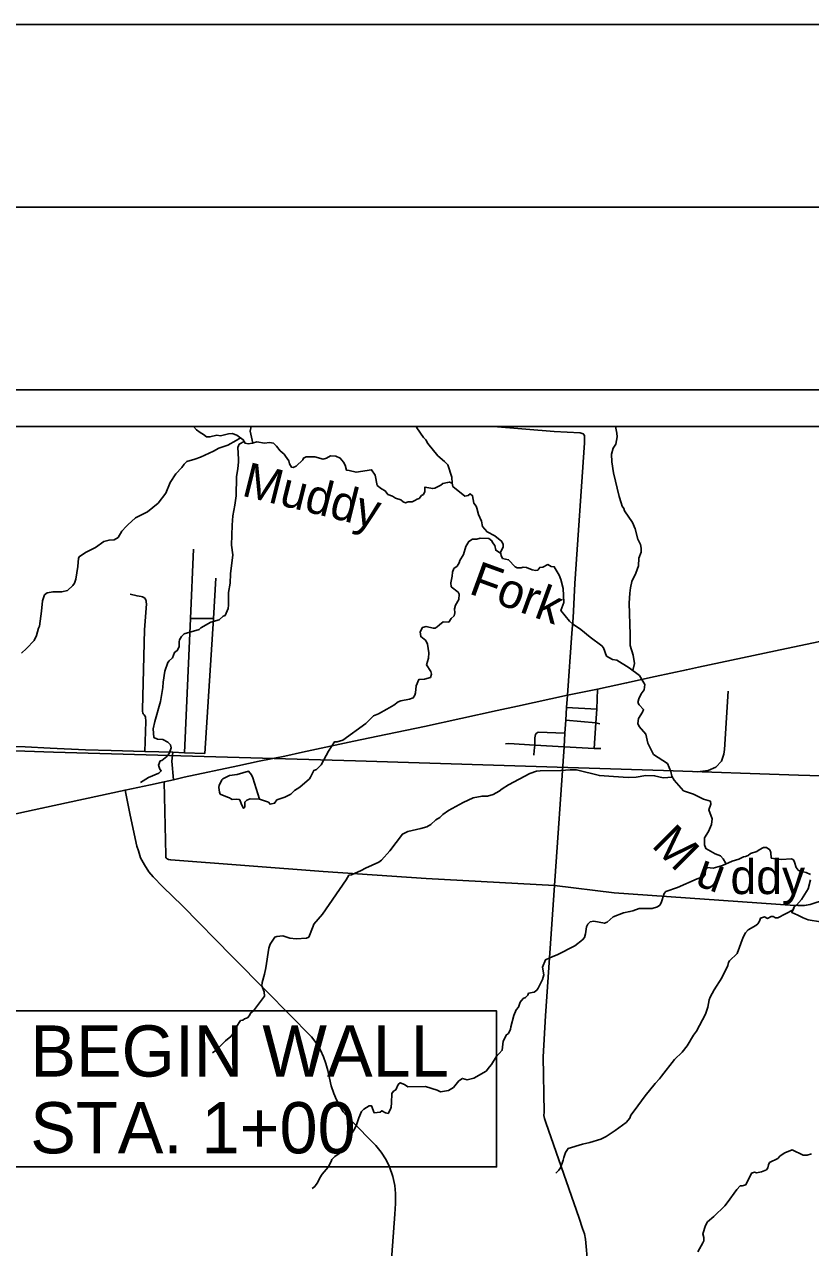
# Model space of a CAD drawing. Extents: x 0 to 34, y 0 to 22.
# Drawn here: x 3.646 to 5.796, y 18.654 to 22 of the extents above; entities that cross this region are included whole.
import ezdxf

# ---------------------------------------------------------------- set-up
doc = ezdxf.new("R2010")
doc.units = 0
for name, color, linetype in [('GM_X_City_Street', 7, 'Continuous'), ('GM_X_Corporation', 7, 'Continuous'), ('GM_X_Minor_Lake', 7, 'Continuous'), ('GM_X_Minor_River', 7, 'Continuous'), ('GM_X_Minor_River_Text', 7, 'Continuous'), ('GM_X_Rail_Line', 7, 'Continuous'), ('GM_X_State_Route', 7, 'Continuous'), ('GM_X_Township_Road', 7, 'Continuous'), ('SH_Border', 7, 'Continuous'), ('SH_Cut_Line', 7, 'Continuous'), ('SH_Data', 7, 'Continuous'), ('SH_Text', 7, 'Continuous')]:
    doc.layers.add(name, color=color, linetype=linetype)

msp = doc.modelspace()

# ---------------------------------------------------------------- linework, layer by layer
at = {"layer": 'GM_X_City_Street'}
for p, q in [((4.1002, 20.3749), (4.1627, 20.3752)), ((5.1287, 20.131), (5.2113, 20.1263))]:
    msp.add_line(p, q, dxfattribs=at)
for points in [[(8.3697, 20.9), (2.1, 20.9)], [(4.0842, 20.007), (4.1002, 20.3749), (4.1085, 20.5648)], [(4.1393, 20.005), (4.1627, 20.3752), (4.1696, 20.4851)], [(3.975, 20.0109), (3.9777, 20.0929), (3.9772, 20.1055), (3.9736, 20.1111), (3.971, 20.1139), (3.9696, 20.1166), (3.9688, 20.1202), (3.9688, 20.1262), (3.9749, 20.3433), (3.9797, 20.4151), (3.979, 20.4196), (3.979, 20.423), (3.9782, 20.4253), (3.976, 20.4291), (3.973, 20.4318), (3.9692, 20.4337), (3.9658, 20.4349), (3.9544, 20.4364), (3.9351, 20.4414)], [(5.2039, 20.0192), (5.2086, 20.0889), (5.2113, 20.1263), (5.2134, 20.1816)], [(5.127, 20.0967), (5.2086, 20.0889), (5.2197, 20.0869)], [(5.0393, 20.001), (5.0402, 20.0138), (5.0416, 20.0279), (5.0417, 20.0281), (5.0422, 20.048), (5.0428, 20.0529), (5.0437, 20.0575), (5.0458, 20.0604), (5.0483, 20.0624), (5.0512, 20.0638), (5.124, 20.0613)], [(3.4131, 20.0315), (3.4572, 20.0306), (3.4702, 20.0303), (3.4891, 20.0292), (3.5108, 20.0284), (3.5458, 20.0271), (3.6215, 20.0244), (3.6483, 20.0233), (3.7162, 20.0202), (3.8134, 20.0158), (3.8829, 20.0135), (3.975, 20.0109), (4.0517, 20.0087), (4.0842, 20.007), (4.1393, 20.005)], [(4.9618, 20.0322), (4.9709, 20.0326), (5.0417, 20.0281), (5.1221, 20.0241), (5.2039, 20.0192), (5.2225, 20.0191)], [(4.0542, 19.9335), (4.0495, 19.9844), (4.0517, 20.0087)], [(4.0285, 19.9277), (4.0325, 19.7272), (4.0325, 19.7203), (4.0344, 19.7188), (4.0367, 19.7173), (4.0405, 19.7158), (4.0462, 19.7143), (4.4631, 19.6827), (4.7449, 19.663), (5.0958, 19.6447)], [(5.0958, 19.6447), (5.259, 19.6246), (5.753, 19.5898), (5.7572, 19.5902), (5.7617, 19.5891), (5.7663, 19.5891), (5.7716, 19.5899), (5.7788, 19.5896), (5.7845, 19.5907), (5.7894, 19.5915), (5.7951, 19.5927), (5.8364, 19.6057)]]:
    msp.add_lwpolyline(points, dxfattribs=at)
at = {"layer": 'GM_X_Corporation'}
msp.add_lwpolyline([(3.4218, 18.4152), (4.6285, 18.3373), (5.2113, 18.299), (5.2682, 18.2953), (5.912, 18.251), (6.0938, 18.2359), (6.2646, 18.2231), (6.3253, 19.1073), (6.3374, 19.2897), (6.3556, 19.5188), (6.3621, 19.6044), (6.385, 20.0884), (6.3883, 20.1254), (6.389, 20.1539), (6.3927, 20.2003), (6.4001, 20.2844), (6.4016, 20.3608), (6.4097, 20.4361), (6.4277, 20.7531), (6.4325, 20.8009), (6.4385, 20.9), (2.1, 20.9)], dxfattribs=at)
at = {"layer": 'GM_X_Minor_Lake'}
for points in [[(4.2889, 19.8806), (4.2705, 19.9384), (4.2671, 19.9471), (4.2584, 19.9574), (4.2281, 19.9483), (4.2069, 19.9453), (4.1883, 19.9363), (4.186, 19.9332), (4.1837, 19.9291), (4.1784, 19.9184), (4.178, 19.912), (4.1795, 19.8995), (4.1814, 19.8942)], [(4.1814, 19.8942), (4.2015, 19.8858), (4.2071, 19.8838), (4.2094, 19.8819), (4.2139, 19.88), (4.2257, 19.8804), (4.2333, 19.8796), (4.2351, 19.8785), (4.2385, 19.8682), (4.2419, 19.8618), (4.2453, 19.8557), (4.2484, 19.8587), (4.2484, 19.8625), (4.2488, 19.8724), (4.2545, 19.878), (4.2632, 19.8811), (4.2889, 19.8806)]]:
    msp.add_lwpolyline(points, dxfattribs=at)
at = {"layer": 'GM_X_Minor_River'}
for points in [[(4.3271, 20.8547), (4.3165, 20.8563), (4.3024, 20.8549), (4.2812, 20.8581), (4.2698, 20.8543), (4.2577, 20.8529), (4.2497, 20.8544), (4.2445, 20.864), (4.2267, 20.8766), (4.2143, 20.8812), (4.2044, 20.8801), (4.1824, 20.8746), (4.1718, 20.8761), (4.1532, 20.8717), (4.1437, 20.8714), (4.1358, 20.8786), (4.1271, 20.8832), (4.1169, 20.8905), (4.1084, 20.9)], [(4.2703, 20.8545), (4.2636, 20.8873), (4.2661, 20.9)], [(4.8155, 20.7449), (4.8145, 20.7612), (4.8037, 20.795), (4.795, 20.8046), (4.7769, 20.8202), (4.7494, 20.8537), (4.7438, 20.8636), (4.737, 20.8701), (4.7189, 20.896), (4.7158, 20.9)], [(5.3099, 20.2324), (5.3139, 20.2517), (5.3103, 20.2741), (5.3025, 20.3007), (5.3026, 20.3314), (5.3001, 20.4164), (5.3014, 20.444), (5.3037, 20.4588), (5.3072, 20.4762), (5.3176, 20.4985), (5.3249, 20.5193), (5.3262, 20.5402), (5.3327, 20.5564), (5.3328, 20.5674), (5.3305, 20.5773), (5.3238, 20.5921), (5.316, 20.6198), (5.3085, 20.637), (5.2871, 20.6693), (5.2852, 20.6754), (5.2807, 20.6822), (5.2781, 20.691), (5.2725, 20.7084), (5.257, 20.7734), (5.2522, 20.8037), (5.2516, 20.8246), (5.2558, 20.8405), (5.2631, 20.8514), (5.2666, 20.8715), (5.2663, 20.8821), (5.2627, 20.9)], [(3.6384, 20.2796), (3.6522, 20.2924), (3.6731, 20.3146), (3.6789, 20.3286), (3.6847, 20.3487), (3.6878, 20.3536), (3.6925, 20.3952), (3.6957, 20.4229), (3.7007, 20.4395), (3.708, 20.4452), (3.7243, 20.4481), (3.7345, 20.4473), (3.7486, 20.448), (3.7637, 20.4517), (3.7782, 20.4649), (3.7828, 20.4713), (3.7863, 20.4823), (3.7925, 20.5171), (3.7942, 20.5398), (3.7969, 20.5448), (3.8151, 20.5564), (3.8406, 20.5688), (3.8634, 20.5857), (3.8775, 20.5894), (3.8911, 20.5904), (3.9022, 20.5964), (3.9121, 20.6134), (3.9239, 20.6266), (3.9293, 20.6312), (3.9499, 20.65), (3.9829, 20.6665), (4.0115, 20.6906), (4.0329, 20.7177), (4.0444, 20.7465), (4.0601, 20.771), (4.0761, 20.788), (4.0826, 20.7974), (4.0906, 20.8042), (4.1123, 20.8105), (4.1278, 20.8161), (4.1632, 20.8322), (4.178, 20.8405), (4.202, 20.8494), (4.2255, 20.8622), (4.2369, 20.8693)], [(4.0256, 20.2004), (4.0298, 20.2306), (4.0386, 20.254), (4.0417, 20.259), (4.0512, 20.2676), (4.0562, 20.282), (4.0642, 20.2869), (4.0692, 20.2975), (4.0689, 20.3111), (4.0701, 20.316), (4.0754, 20.3251), (4.0827, 20.3326), (4.1237, 20.3449), (4.1286, 20.3494), (4.1556, 20.3648), (4.1788, 20.3711), (4.1895, 20.3809), (4.1948, 20.3832), (4.2029, 20.4017), (4.204, 20.4115), (4.2039, 20.446), (4.2085, 20.471), (4.2094, 20.4968), (4.2158, 20.5487), (4.2125, 20.5756), (4.214, 20.6298), (4.216, 20.6552), (4.2211, 20.6848), (4.2251, 20.7102), (4.2261, 20.7628), (4.23, 20.7856), (4.2313, 20.8026), (4.2313, 20.8106), (4.2296, 20.8424), (4.2334, 20.8515), (4.247, 20.8594)], [(5.343, 20.1944), (5.3278, 20.2187), (5.2998, 20.2401), (5.2662, 20.2611), (5.2545, 20.2623), (5.2375, 20.2719), (5.2292, 20.2943), (5.2251, 20.3), (5.193, 20.3234), (5.1674, 20.3451), (5.1447, 20.36), (5.1364, 20.3673), (5.1131, 20.3966), (5.1208, 20.4182), (5.1195, 20.4569), (5.1128, 20.4815), (5.1079, 20.493), (5.0948, 20.5162), (5.0868, 20.5166), (5.077, 20.5223), (5.0641, 20.5152), (5.0553, 20.5145), (5.0496, 20.5069), (5.0447, 20.5062), (5.0345, 20.5082), (5.0193, 20.514), (5.0102, 20.5155), (5.0045, 20.5133), (4.9932, 20.5137), (4.9879, 20.5164), (4.9702, 20.5355), (4.9535, 20.539), (4.9494, 20.5474), (4.9475, 20.5565), (4.9548, 20.5701), (4.9548, 20.5773), (4.9511, 20.5856), (4.9326, 20.6009), (4.9114, 20.6117), (4.899, 20.6269), (4.8957, 20.6413), (4.8878, 20.6592), (4.8834, 20.6763), (4.8811, 20.6824), (4.8747, 20.6907), (4.8714, 20.7108), (4.8654, 20.7154), (4.8597, 20.7109), (4.8506, 20.7098), (4.8177, 20.7358), (4.8155, 20.7449), (4.808, 20.748), (4.803, 20.7465), (4.7901, 20.7443), (4.7848, 20.7394), (4.7681, 20.7312), (4.7627, 20.7301), (4.7412, 20.7344), (4.7407, 20.7222), (4.7373, 20.7139), (4.7323, 20.7117), (4.7254, 20.7034), (4.7197, 20.7011), (4.714, 20.6978), (4.706, 20.6936), (4.6954, 20.6937), (4.6882, 20.6911), (4.6818, 20.6938), (4.6758, 20.6991), (4.661, 20.7041), (4.6523, 20.7099), (4.6402, 20.7137), (4.6327, 20.7236), (4.6221, 20.7294), (4.6108, 20.7389), (4.6049, 20.7667), (4.5955, 20.7819), (4.553, 20.7749), (4.534, 20.7796), (4.5265, 20.7808), (4.5235, 20.7941), (4.519, 20.8024), (4.5096, 20.8131), (4.4975, 20.8189), (4.4831, 20.8197), (4.4721, 20.8133), (4.4629, 20.8103), (4.4402, 20.8173), (4.4167, 20.8171), (4.4091, 20.8137), (4.4076, 20.8088), (4.3893, 20.7911), (4.3813, 20.7877), (4.376, 20.7889), (4.3711, 20.7976), (4.3689, 20.806), (4.3599, 20.8189), (4.3561, 20.8246), (4.3455, 20.8338), (4.3358, 20.8467), (4.3271, 20.8547)], [(4.7171, 20.1901), (4.7242, 20.2075), (4.7401, 20.2085), (4.7564, 20.2137), (4.7595, 20.2228), (4.7577, 20.23), (4.746, 20.2479), (4.751, 20.2665), (4.7515, 20.2805), (4.7486, 20.3048), (4.7433, 20.3147), (4.7298, 20.3254), (4.7283, 20.3386), (4.7344, 20.35), (4.7443, 20.3533), (4.764, 20.3479), (4.7689, 20.3486), (4.7743, 20.3524), (4.7807, 20.3573), (4.791, 20.3652), (4.8062, 20.3647), (4.8127, 20.3745), (4.8211, 20.3817), (4.823, 20.39), (4.8223, 20.401), (4.825, 20.4112), (4.8338, 20.4267), (4.835, 20.4415), (4.8324, 20.4465), (4.8132, 20.4614), (4.8117, 20.472), (4.816, 20.4905), (4.8164, 20.5019), (4.8203, 20.5114), (4.829, 20.5181), (4.8348, 20.5272), (4.8371, 20.5336), (4.8463, 20.5495), (4.8528, 20.5718), (4.8609, 20.5858), (4.8711, 20.5918), (4.8829, 20.5917), (4.8924, 20.5943), (4.9163, 20.5934), (4.9246, 20.5877), (4.9261, 20.5828), (4.9325, 20.5744), (4.9347, 20.5615), (4.9481, 20.5534)], [(4.0256, 20.2004), (4.0248, 20.186), (4.0183, 20.1477), (4.0023, 20.0934), (3.9985, 20.0726), (3.9996, 20.0494), (4.0102, 20.0445), (4.0249, 20.0437), (4.0385, 20.036), (4.0454, 20.0288), (4.0472, 20.0208), (4.0415, 20.0057), (4.0358, 19.9973), (4.0218, 19.9864), (4.0169, 19.9852), (4.013, 19.9731), (4.0168, 19.9628), (4.0202, 19.9579), (4.0141, 19.9515), (3.9853, 19.9401), (3.9637, 19.9261)], [(4.7171, 20.1901), (4.7155, 20.1712), (4.714, 20.1651), (4.7094, 20.1575), (4.6992, 20.1537), (4.6753, 20.1492), (4.6681, 20.1466), (4.656, 20.1375), (4.637, 20.1266), (4.6147, 20.1141), (4.6007, 20.1084), (4.5798, 20.0876), (4.5168, 20.0418), (4.5017, 20.0377), (4.4941, 20.0377), (4.4778, 20.0115), (4.4576, 19.9744), (4.4447, 19.9615), (4.4371, 19.9585), (4.4284, 19.941), (4.4254, 19.9361), (4.3996, 19.913), (4.3848, 19.9043), (4.3749, 19.8945), (4.3578, 19.8858), (4.3366, 19.8786), (4.3302, 19.8695), (4.318, 19.8665), (4.3131, 19.8722), (4.2889, 19.8806)], [(5.5624, 19.7022), (5.5628, 19.7066), (5.5568, 19.7172), (5.5496, 19.7252), (5.5352, 19.7305), (5.5095, 19.7454), (5.5061, 19.7553), (5.5061, 19.7743), (5.5164, 19.7917), (5.5248, 19.811), (5.5263, 19.8266), (5.518, 19.8509), (5.523, 19.8664), (5.5219, 19.8748), (5.5033, 19.8809), (5.4753, 19.8939), (5.4704, 19.8958), (5.4485, 19.9031), (5.4224, 19.9327), (5.4167, 19.9434), (5.4141, 19.9559), (5.4047, 19.9779), (5.3665, 20.0027), (5.3507, 20.0338), (5.345, 20.0585), (5.3269, 20.0791), (5.3231, 20.0878), (5.325, 20.1015), (5.3364, 20.1185), (5.3391, 20.1257), (5.3274, 20.1383), (5.3232, 20.1447), (5.3259, 20.1554), (5.3324, 20.169), (5.3411, 20.1796), (5.343, 20.1944)], [(5.4183, 19.9404), (5.3925, 19.9392), (5.3694, 19.9446), (5.3456, 19.945), (5.3187, 19.9409), (5.2971, 19.9398), (5.2566, 19.9422), (5.2183, 19.945), (5.1559, 19.9603), (5.1388, 19.9607), (5.1127, 19.9585), (5.0563, 19.9582), (5.0468, 19.9571), (5.0282, 19.9507), (4.9702, 19.9201), (4.9528, 19.9087), (4.9441, 19.9019), (4.9282, 19.8929), (4.9126, 19.8887), (4.8975, 19.8891), (4.8728, 19.8839), (4.8459, 19.8714), (4.8054, 19.8499), (4.7898, 19.8389), (4.7822, 19.8306), (4.7712, 19.8237), (4.7572, 19.8116), (4.7462, 19.8052), (4.7303, 19.8003), (4.6947, 19.792), (4.6795, 19.7849), (4.645, 19.739), (4.6222, 19.7136), (4.6154, 19.7083), (4.5786, 19.6917), (4.5672, 19.6849), (4.5407, 19.6736), (4.5335, 19.6721), (4.5255, 19.6596), (4.4613, 19.566), (4.4378, 19.5383), (4.4355, 19.533), (4.4237, 19.503), (4.4177, 19.5), (4.3893, 19.4982), (4.3715, 19.5001), (4.3525, 19.507), (4.3359, 19.5051), (4.3309, 19.5033), (4.3184, 19.4839), (4.3142, 19.4725), (4.3065, 19.4187), (4.3027, 19.402), (4.2959, 19.3785), (4.2951, 19.3697), (4.3015, 19.3534), (4.3022, 19.3416), (4.2722, 19.3011), (4.2643, 19.295), (4.2616, 19.289), (4.2559, 19.2818), (4.2483, 19.2791), (4.243, 19.2761), (4.237, 19.2746), (4.2248, 19.2568), (4.2229, 19.2496), (4.2172, 19.2393), (4.2104, 19.231), (4.1959, 19.2189), (4.1701, 19.1935), (4.1607, 19.1863)], [(5.796, 19.6741), (5.7835, 19.6799), (5.7672, 19.6833), (5.7616, 19.6864), (5.7563, 19.6936), (5.7522, 19.7084), (5.7488, 19.7149), (5.7438, 19.7172), (5.7151, 19.7157), (5.7075, 19.7161), (5.6882, 19.7192), (5.6871, 19.7347), (5.6841, 19.7416), (5.675, 19.7481), (5.6674, 19.7481), (5.6549, 19.742), (5.6485, 19.7371), (5.6318, 19.7322), (5.6253, 19.7265), (5.6181, 19.7239), (5.6128, 19.7228), (5.5996, 19.716), (5.5818, 19.7111), (5.5552, 19.699), (5.5295, 19.6915), (5.5128, 19.6934), (5.5082, 19.6858), (5.5071, 19.6748), (5.5029, 19.6676), (5.4855, 19.6623), (5.432, 19.6389), (5.4002, 19.6276), (5.3953, 19.6227), (5.3869, 19.5965), (5.3835, 19.5908), (5.3774, 19.5859), (5.3622, 19.5814), (5.3274, 19.5811), (5.31, 19.5751), (5.302, 19.5728), (5.2846, 19.5698), (5.2562, 19.5581), (5.2395, 19.5441), (5.2319, 19.5411), (5.2031, 19.5464), (5.1929, 19.5446), (5.1864, 19.5389), (5.1834, 19.5309), (5.1807, 19.512), (5.1777, 19.5021), (5.172, 19.4953), (5.1515, 19.4794), (5.1026, 19.4544), (5.0908, 19.4499), (5.0708, 19.4409), (5.0631, 19.4204), (5.0665, 19.3999), (5.0631, 19.3874), (5.0509, 19.3631)], [(5.8226, 19.545), (5.7893, 19.5504), (5.7753, 19.5561), (5.7613, 19.5634), (5.7443, 19.5703), (5.7519, 19.5873), (5.7572, 19.5904), (5.7709, 19.6059), (5.7891, 19.6354), (5.796, 19.6601)], [(5.7498, 19.5827), (5.7485, 19.5775), (5.7064, 19.5555), (5.7, 19.5559), (5.6935, 19.5594), (5.6879, 19.559), (5.6784, 19.5541), (5.6697, 19.5583), (5.6587, 19.5545), (5.656, 19.5466), (5.6515, 19.5397), (5.6462, 19.5348), (5.6253, 19.5227), (5.6181, 19.5148), (5.6116, 19.5026), (5.5949, 19.4586), (5.574, 19.4386), (5.5717, 19.4333), (5.5691, 19.4253), (5.5527, 19.3919), (5.5318, 19.3586), (5.5208, 19.3385), (5.5185, 19.3313), (5.5147, 19.3112), (5.5082, 19.2926), (5.4839, 19.246), (5.4759, 19.235), (5.4584, 19.2058), (5.4444, 19.188), (5.4239, 19.1679), (5.3878, 19.1224), (5.3825, 19.1149), (5.3707, 19.1027), (5.3434, 19.0686), (5.3138, 19.0281), (5.3047, 19.0156), (5.3012, 19.008), (5.2914, 18.9963), (5.2614, 18.9736), (5.2364, 18.9573), (5.222, 18.9501), (5.1921, 18.9411), (5.172, 18.9369), (5.1326, 18.9249), (5.1254, 18.9139), (5.1212, 18.8999), (5.1196, 18.893), (5.1116, 18.8718), (5.1078, 18.8657), (5.0991, 18.857)], [(5.0509, 19.3631), (5.0471, 19.3582), (5.0403, 19.3525), (5.0247, 19.3495), (5.0228, 19.3446), (5.016, 19.3377), (5.01, 19.3355), (5.0016, 19.3249), (4.9974, 19.3116), (4.9906, 19.3044), (4.9841, 19.2885), (4.9765, 19.2574), (4.9757, 19.2513), (4.9696, 19.2395), (4.9647, 19.2361), (4.9548, 19.2187), (4.9525, 19.1933), (4.9365, 19.1755), (4.9232, 19.1542), (4.9176, 19.1482), (4.9084, 19.1364), (4.8747, 19.1168), (4.8565, 19.1123), (4.844, 19.1165), (4.8338, 19.1097), (4.8194, 19.0918), (4.8053, 19.0831), (4.7837, 19.0798), (4.7747, 19.0844), (4.7429, 19.0943), (4.6944, 19.0933), (4.6853, 19.0997), (4.6736, 19.1047), (4.6679, 19.0998), (4.6618, 19.0854), (4.655, 19.0812), (4.6504, 19.0751), (4.65, 19.0493), (4.6488, 19.0376), (4.6473, 19.0323), (4.6405, 19.0209), (4.6333, 19.022), (4.6238, 19.0278), (4.6189, 19.0244), (4.6022, 19.0225), (4.5951, 19.0415), (4.589, 19.0415), (4.5742, 19.0324), (4.5682, 19.026), (4.5606, 19.0089), (4.5541, 18.9892), (4.5495, 18.9797), (4.5298, 18.9464), (4.5199, 18.9255), (4.507, 18.9107), (4.4948, 18.9028), (4.4869, 18.8945), (4.4846, 18.8892), (4.4766, 18.8736), (4.4607, 18.8543), (4.4538, 18.8441), (4.4485, 18.8323), (4.4398, 18.8209), (4.4326, 18.8149)], [(5.7982, 18.9097), (5.7865, 18.9063), (5.7759, 18.9067), (5.7456, 18.9208), (5.7255, 18.9125), (5.7123, 18.9042), (5.7062, 18.8974), (5.6838, 18.886), (5.6804, 18.8804), (5.6789, 18.872), (5.6751, 18.866), (5.6614, 18.8607), (5.6482, 18.8584), (5.6425, 18.8596), (5.6346, 18.8573), (5.6186, 18.8251), (5.6084, 18.8225), (5.6034, 18.8228), (5.5943, 18.813), (5.5677, 18.7762), (5.5609, 18.7683), (5.5317, 18.7391), (5.5142, 18.724), (5.5082, 18.7145), (5.5009, 18.6914), (5.5043, 18.6815), (5.5039, 18.6724), (5.5009, 18.6667), (5.4879, 18.6421)]]:
    msp.add_lwpolyline(points, dxfattribs=at)
at = {"layer": 'GM_X_Rail_Line'}
for points in [[(5.4863, 19.9556), (5.5158, 19.9586), (5.5367, 19.9676), (5.5518, 19.9845), (5.5587, 20.0033), (5.5602, 20.0165), (5.5704, 20.1759)], [(2.1, 20.0629), (2.3112, 20.0558), (2.9425, 20.0365), (3.7259, 20.0086), (4.1377, 19.997), (4.5514, 19.9851), (5.3933, 19.9589), (5.7629, 19.946), (6.3762, 19.9275), (7.0828, 19.9047), (7.6933, 19.8843), (7.9626, 19.8754), (8.7713, 19.8495), (8.9, 19.8461)]]:
    msp.add_lwpolyline(points, dxfattribs=at)
at = {"layer": 'GM_X_State_Route'}
for points in [[(5.489, 20.2413), (5.7302, 20.2925), (5.9124, 20.3309), (6.0297, 20.3545), (6.1069, 20.3719)], [(4.994, 20.1353), (5.1313, 20.1649), (5.2134, 20.1816), (5.2927, 20.1987), (5.3708, 20.2159), (5.4565, 20.2344), (5.489, 20.2413)], [(4.6121, 20.0526), (4.7398, 20.0792), (4.9391, 20.1234), (4.994, 20.1353)], [(4.4062, 20.0088), (4.5472, 20.0391), (4.6121, 20.0526)], [(4.2296, 19.9715), (4.2883, 19.984), (4.3582, 19.9985), (4.4062, 20.0088)], [(4.0414, 19.9306), (4.0542, 19.9335), (4.0827, 19.9403), (4.2296, 19.9715)], [(2.5724, 19.6181), (2.9064, 19.6877), (3.0584, 19.7179), (3.1671, 19.741), (3.2909, 19.7685), (3.3959, 19.7912), (3.6939, 19.8555), (3.9212, 19.9052), (3.9906, 19.9196), (4.0285, 19.9277), (4.0414, 19.9306)]]:
    msp.add_lwpolyline(points, dxfattribs=at)
at = {"layer": 'GM_X_Township_Road'}
for points in [[(5.1313, 20.1649), (5.143, 20.3343), (5.1469, 20.3763), (5.1508, 20.4705), (5.1776, 20.8554), (5.1779, 20.8696), (5.1773, 20.875), (5.174, 20.8799), (5.1658, 20.8826), (5.0945, 20.8862), (4.929, 20.9)], [(5.0958, 19.6447), (5.1221, 20.0241), (5.124, 20.0613), (5.127, 20.0967), (5.1287, 20.131), (5.1313, 20.1649)], [(4.6439, 18.5348), (4.6588, 18.7455), (4.6607, 18.7738), (4.6607, 18.8016), (4.6591, 18.8239), (4.6536, 18.8479), (4.6443, 18.8745), (4.6355, 18.8934), (4.622, 18.9149), (4.6073, 18.933), (4.5892, 18.9515), (4.5576, 18.9827), (4.5416, 18.9991), (4.5268, 19.0151), (4.518, 19.0252), (4.5083, 19.0408), (4.4995, 19.0581), (4.4919, 19.0749), (4.4851, 19.096), (4.4754, 19.1381), (4.47, 19.157), (4.4641, 19.1756), (4.4557, 19.1933), (4.4455, 19.2109), (4.4308, 19.2303), (4.3087, 19.3546), (4.2143, 19.4502), (4.0783, 19.5883), (4.0246, 19.6408), (3.9986, 19.6682), (3.9867, 19.6815), (3.9741, 19.7004), (3.9639, 19.7197), (3.9576, 19.7393), (3.9539, 19.7521), (3.9356, 19.8368), (3.9212, 19.9052)], [(5.2116, 18.2984), (5.2059, 18.3925), (5.1805, 18.6769), (5.1777, 18.6909), (5.1724, 18.7062), (5.1629, 18.7337), (5.0721, 18.9955), (5.0684, 19.0065), (5.0666, 19.0147), (5.067, 19.0245), (5.0644, 19.1757), (5.0714, 19.2876), (5.0958, 19.6447)]]:
    msp.add_lwpolyline(points, dxfattribs=at)
at = {"layer": 'SH_Border'}
msp.add_lwpolyline([(1.5, 21.5), (33.5, 21.5), (33.5, 0.5), (1.5, 0.5)], close=True, dxfattribs=at)
at = {"layer": 'SH_Cut_Line'}
for points in [[(0, 0), (34, 0), (34, 22), (0, 22)], [(8.9, 15.4827), (8.9, 20.9), (2.1, 20.9), (2.1, 15.9442), (2.2903, 15.9292), (2.5827, 15.9132), (2.6921, 15.9056), (2.7799, 15.8989), (2.8362, 15.8952), (3.3132, 15.8609), (3.9945, 15.8088), (4.2803, 15.787), (4.5905, 15.7634), (4.92, 15.7429), (5.0952, 15.7318), (5.9419, 15.6782), (6.1109, 15.6683), (6.4, 15.6498), (6.624, 15.6351), (6.838, 15.6206), (7.6503, 15.5653), (8.6741, 15.4976)]]:
    msp.add_lwpolyline(points, close=True, dxfattribs=at)
at = {"layer": 'SH_Data'}
msp.add_line((2, 21), (9, 21), dxfattribs=at)
at = {"layer": 'SH_Text'}
msp.add_lwpolyline([(3.6186, 19.301), (4.9371, 19.301), (4.9371, 18.8742), (3.6186, 18.8742)], close=True, dxfattribs=at)

# ---------------------------------------------------------------- texts
at = {"layer": 'GM_X_Minor_River_Text'}
for s, height, rotation, p in [('Muddy', 0.09469, 346.0013, (4.2374, 20.7115)), ('Fork', 0.09469, 340.0005, (4.8583, 20.4441)), ('M', 0.0947, 314.9998, (5.3577, 19.7523)), ('u', 0.0947, 339.9986, (5.4759, 19.6468)), ('ddy', 0.09469, 359.9981, (5.5767, 19.6208))]:
    msp.add_text(s, height=height, rotation=rotation, dxfattribs=at).set_placement(p)
at = {"layer": 'SH_Text'}
for s, p in [('BEGIN WALL    ', (3.6621, 19.1215)), ('STA. 1+00        ', (3.6621, 18.9115))]:
    msp.add_text(s, height=0.14, dxfattribs=at).set_placement(p)

doc.saveas('drawing.dxf')
